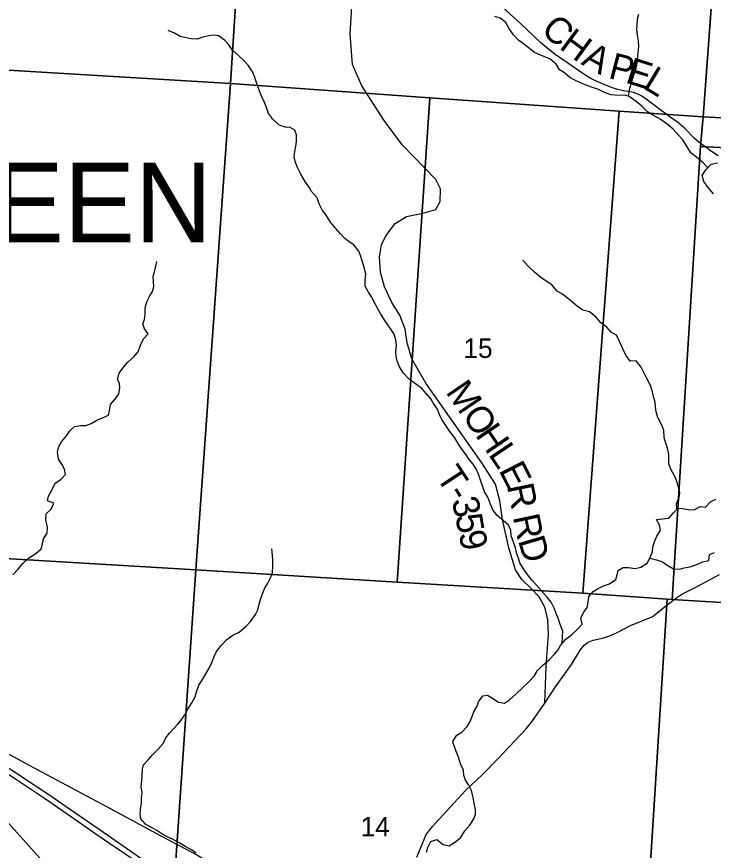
# Model space of a CAD drawing. Extents: x 39.8 to 73.8, y 13 to 35.
# Drawn here: x 45.973 to 47.463, y 29.389 to 31.174 of the extents above; entities that cross this region are included whole.
import ezdxf

# ---------------------------------------------------------------- set-up
doc = ezdxf.new("R2010")
doc.units = 0
for name, color, linetype in [('GM_X_Corporation', 7, 'Continuous'), ('GM_X_County_Road', 7, 'Continuous'), ('GM_X_Minor_River', 7, 'Continuous'), ('GM_X_Rail_Line', 7, 'Continuous'), ('GM_X_Section_Text', 7, 'Continuous'), ('GM_X_State_Route', 7, 'Continuous'), ('GM_X_Township_Road', 7, 'Continuous'), ('GM_X_Township_Road_Text', 7, 'Continuous'), ('GM_X_Township_Text', 7, 'Continuous'), ('GM_X_US_Route', 7, 'Continuous')]:
    doc.layers.add(name, color=color, linetype=linetype)

msp = doc.modelspace()

# ---------------------------------------------------------------- linework, layer by layer
at = {"layer": 'GM_X_Corporation'}
for points in [[(46.4973, 32.0662), (46.4309, 31.0306), (45.4314, 31.091), (45.5069, 32.1262)], [(46.4973, 32.0662), (47.514, 31.9975), (47.4987, 31.7536), (47.4692, 31.3373), (47.4415, 30.9593), (47.2622, 30.9716), (46.8571, 31.0001), (46.4309, 31.0306)], [(47.4692, 31.3373), (48.4841, 31.2738), (48.4569, 30.9045), (47.4415, 30.9593)], [(45.4314, 31.091), (46.4309, 31.0306), (46.3565, 29.9898), (45.3612, 30.049), (45.3568, 30.0492)], [(46.8571, 31.0001), (46.7869, 29.9637), (46.3565, 29.9898), (46.4309, 31.0306)], [(47.2622, 30.9716), (47.1839, 29.9397), (46.7869, 29.9637), (46.8571, 31.0001)], [(47.4415, 30.9593), (47.4356, 30.8958), (47.3755, 29.9267), (47.3645, 29.9274), (47.1839, 29.9397), (47.2622, 30.9716)], [(47.4415, 30.9593), (48.4569, 30.9045), (48.4524, 30.8427), (48.1497, 30.8585), (47.6837, 30.8829), (47.4356, 30.8958)], [(47.6837, 30.8829), (47.6104, 29.9124), (47.3755, 29.9267), (47.4356, 30.8958)], [(45.3612, 30.049), (46.3565, 29.9898), (46.2858, 28.9647), (45.2916, 29.0179)], [(46.3565, 29.9898), (46.7869, 29.9637), (47.1839, 29.9397), (47.3645, 29.9274), (47.3001, 28.9116), (46.2858, 28.9647)], [(47.3645, 29.9274), (47.3755, 29.9267), (47.6104, 29.9124), (48.0851, 29.8835), (48.3814, 29.8655), (48.3118, 28.8573), (47.3001, 28.9116)]]:
    msp.add_lwpolyline(points, close=True, dxfattribs=at)
at = {"layer": 'GM_X_County_Road'}
msp.add_lwpolyline([(45.8429, 29.6563), (45.8641, 29.6449), (46.0264, 29.5578), (46.1656, 29.4834), (46.282, 29.4208), (46.3589, 29.3795), (46.3727, 29.3714), (46.3799, 29.3664)], dxfattribs=at)
at = {"layer": 'GM_X_Minor_River'}
for p, q in [((47.3015, 31.1688), (47.3037, 31.179)), ((47.0076, 31.1709), (46.9959, 31.1746)), ((47.0194, 31.1618), (47.0076, 31.1709)), ((47.0259, 31.1497), (47.0194, 31.1618)), ((47.3004, 31.1566), (47.3015, 31.1688)), ((47.0358, 31.1353), (47.0259, 31.1497)), ((47.2997, 31.1472), (47.3004, 31.1566)), ((47.3009, 31.1343), (47.2997, 31.1472)), ((47.0472, 31.1232), (47.0358, 31.1353)), ((47.0601, 31.1134), (47.0472, 31.1232)), ((47.3032, 31.1214), (47.3009, 31.1343)), ((47.0707, 31.1051), (47.0601, 31.1134)), ((47.081, 31.0975), (47.0707, 31.1051)), ((47.3025, 31.0963), (47.304, 31.1108)), ((47.304, 31.1108), (47.3032, 31.1214)), ((47.0909, 31.093), (47.081, 31.0975)), ((47.1144, 31.0832), (47.0909, 31.093)), ((47.3011, 31.0831), (47.3025, 31.0963)), ((47.1269, 31.0723), (47.1144, 31.0832)), ((47.1346, 31.0601), (47.1269, 31.0723)), ((47.2966, 31.058), (47.2996, 31.0702)), ((47.2996, 31.0702), (47.3011, 31.0831)), ((47.1448, 31.0537), (47.1346, 31.0601)), ((47.1566, 31.0435), (47.1448, 31.0537)), ((47.2929, 31.047), (47.2966, 31.058)), ((47.1668, 31.0382), (47.1566, 31.0435)), ((47.1858, 31.0292), (47.1668, 31.0382)), ((47.2884, 31.0326), (47.2929, 31.047)), ((47.2048, 31.0224), (47.1858, 31.0292)), ((47.2181, 31.0179), (47.2048, 31.0224)), ((47.2321, 31.0108), (47.2181, 31.0179)), ((47.2819, 31.0037), (47.2851, 31.0208)), ((47.2851, 31.0208), (47.2884, 31.0326)), ((47.2446, 31.007), (47.2321, 31.0108)), ((47.2598, 31.0052), (47.2446, 31.007)), ((47.2738, 31.0056), (47.2598, 31.0052)), ((47.2836, 31.0033), (47.2738, 31.0056)), ((47.2981, 30.9924), (47.2836, 31.0033)), ((47.3102, 30.9822), (47.2981, 30.9924)), ((47.3224, 30.9705), (47.3102, 30.9822)), ((47.3357, 30.9625), (47.3224, 30.9705)), ((47.3493, 30.9546), (47.3357, 30.9625)), ((47.3649, 30.944), (47.3493, 30.9546)), ((47.3778, 30.9331), (47.3649, 30.944)), ((47.3893, 30.9198), (47.3778, 30.9331)), ((47.398, 30.91), (47.3893, 30.9198)), ((47.4072, 30.8956), (47.398, 30.91)), ((47.4155, 30.8824), (47.4072, 30.8956)), ((47.4277, 30.8729), (47.4155, 30.8824)), ((47.4418, 30.8612), (47.4277, 30.8729)), ((47.4514, 30.8507), (47.4418, 30.8612)), ((47.4471, 30.8461), (47.4588, 30.8586)), ((47.4588, 30.8586), (47.4724, 30.8609)), ((47.4396, 30.8343), (47.4471, 30.8461)), ((47.4431, 30.821), (47.4396, 30.8343)), ((47.4526, 30.8081), (47.4431, 30.821)), ((47.4636, 30.7949), (47.4526, 30.8081)), ((46.2711, 30.6398), (46.2733, 30.6496)), ((47.0667, 30.6408), (47.056, 30.6529)), ((47.0808, 30.6271), (47.0667, 30.6408)), ((46.2655, 30.6181), (46.2678, 30.6276)), ((46.2678, 30.6276), (46.2711, 30.6398)), ((47.0944, 30.6154), (47.0808, 30.6271)), ((46.2663, 30.6064), (46.2655, 30.6181)), ((46.2668, 30.5961), (46.2663, 30.6064)), ((47.1077, 30.6064), (47.0944, 30.6154)), ((47.1176, 30.5996), (47.1077, 30.6064)), ((46.2638, 30.5855), (46.2668, 30.5961)), ((47.1294, 30.5863), (47.1176, 30.5996)), ((46.2518, 30.5634), (46.2578, 30.5748)), ((46.2578, 30.5748), (46.2638, 30.5855)), ((47.1404, 30.5799), (47.1294, 30.5863)), ((47.151, 30.572), (47.1404, 30.5799)), ((47.1632, 30.5622), (47.151, 30.572)), ((46.2484, 30.5509), (46.2518, 30.5634)), ((47.1731, 30.5535), (47.1632, 30.5622)), ((47.1845, 30.5455), (47.1731, 30.5535)), ((46.247, 30.5259), (46.2481, 30.5373)), ((46.2481, 30.5373), (46.2484, 30.5509)), ((47.1985, 30.5418), (47.1845, 30.5455)), ((47.2118, 30.5312), (47.1985, 30.5418)), ((46.2429, 30.5164), (46.247, 30.5259)), ((46.2467, 30.5058), (46.2429, 30.5164)), ((47.2225, 30.5183), (47.2118, 30.5312)), ((47.2354, 30.5093), (47.2225, 30.5183)), ((46.2547, 30.4952), (46.2467, 30.5058)), ((47.2449, 30.4987), (47.2354, 30.5093)), ((47.2559, 30.4919), (47.2449, 30.4987)), ((46.2381, 30.4708), (46.2445, 30.4845)), ((46.2445, 30.4845), (46.2547, 30.4952)), ((47.2624, 30.4786), (47.2559, 30.4919)), ((46.2329, 30.4564), (46.2381, 30.4708)), ((47.27, 30.4627), (47.2624, 30.4786)), ((47.2762, 30.4495), (47.27, 30.4627)), ((46.211, 30.4347), (46.2231, 30.4454)), ((46.2231, 30.4454), (46.2329, 30.4564)), ((47.2857, 30.4362), (47.2762, 30.4495)), ((46.2024, 30.4244), (46.211, 30.4347)), ((47.2986, 30.4374), (47.2857, 30.4362)), ((47.3088, 30.4238), (47.2986, 30.4374)), ((46.1892, 30.3982), (46.1926, 30.4111)), ((46.1926, 30.4111), (46.2024, 30.4244)), ((47.3157, 30.4105), (47.3088, 30.4238)), ((47.3214, 30.3992), (47.3157, 30.4105)), ((46.1934, 30.3888), (46.1892, 30.3982)), ((47.3287, 30.3844), (47.3214, 30.3992)), ((46.1916, 30.366), (46.1939, 30.3793)), ((46.1939, 30.3793), (46.1934, 30.3888)), ((47.3333, 30.3708), (47.3287, 30.3844)), ((46.1826, 30.3538), (46.1916, 30.366)), ((47.336, 30.3582), (47.3333, 30.3708)), ((47.3387, 30.3488), (47.336, 30.3582)), ((46.1721, 30.3307), (46.1739, 30.3436)), ((46.1739, 30.3436), (46.1826, 30.3538)), ((47.3399, 30.3381), (47.3387, 30.3488)), ((47.3411, 30.3279), (47.3399, 30.3381)), ((46.157, 30.3151), (46.1695, 30.3212)), ((46.1695, 30.3212), (46.1721, 30.3307)), ((47.3441, 30.3184), (47.3411, 30.3279)), ((46.1211, 30.2986), (46.1328, 30.3028)), ((46.1328, 30.3028), (46.1449, 30.3101)), ((46.1449, 30.3101), (46.157, 30.3151)), ((47.348, 30.3086), (47.3441, 30.3184)), ((47.3537, 30.298), (47.348, 30.3086)), ((46.0799, 30.2765), (46.0871, 30.2871)), ((46.0871, 30.2871), (46.0969, 30.2967)), ((46.0969, 30.2967), (46.1101, 30.2986)), ((46.1101, 30.2986), (46.1211, 30.2986)), ((47.3575, 30.2881), (47.3537, 30.298)), ((47.3583, 30.2733), (47.3575, 30.2881)), ((46.069, 30.2636), (46.0799, 30.2765)), ((47.361, 30.2631), (47.3583, 30.2733)), ((46.0608, 30.2419), (46.0638, 30.2541)), ((46.0638, 30.2541), (46.069, 30.2636)), ((47.3652, 30.2502), (47.361, 30.2631)), ((47.3683, 30.2377), (47.3652, 30.2502)), ((46.0627, 30.2271), (46.0608, 30.2419)), ((47.3684, 30.2271), (47.3683, 30.2377)), ((46.0696, 30.2161), (46.0627, 30.2271)), ((46.0753, 30.2052), (46.0696, 30.2161)), ((47.368, 30.2169), (47.3684, 30.2271)), ((47.3734, 30.2036), (47.368, 30.2169)), ((46.0776, 30.1942), (46.0753, 30.2052)), ((47.3806, 30.1911), (47.3734, 30.2036)), ((46.0554, 30.1751), (46.0675, 30.1831)), ((46.0675, 30.1831), (46.0776, 30.1942)), ((47.3845, 30.1809), (47.3806, 30.1911)), ((47.3891, 30.1676), (47.3845, 30.1809)), ((46.0415, 30.1474), (46.049, 30.1618)), ((46.049, 30.1618), (46.0554, 30.1751)), ((47.3914, 30.1547), (47.3891, 30.1676)), ((46.0393, 30.1379), (46.0415, 30.1474)), ((47.3847, 30.1319), (47.3903, 30.1448)), ((47.3903, 30.1448), (47.3914, 30.1547)), ((46.0529, 30.1323), (46.0393, 30.1379)), ((46.0469, 30.1197), (46.0529, 30.1323)), ((47.3851, 30.1192), (47.3847, 30.1319)), ((46.0357, 30.0969), (46.0364, 30.1098)), ((46.0364, 30.1098), (46.0469, 30.1197)), ((46.0391, 30.0814), (46.0357, 30.0969)), ((46.0388, 30.0685), (46.0391, 30.0814)), ((46.0287, 30.0457), (46.0305, 30.0559)), ((46.0305, 30.0559), (46.0388, 30.0685)), ((46.014, 30.0248), (46.0257, 30.0351)), ((46.0257, 30.0351), (46.0287, 30.0457)), ((46.5203, 30.0211), (46.5191, 30.0347)), ((45.9985, 30.0145), (46.014, 30.0248)), ((46.5211, 30.0104), (46.5203, 30.0211)), ((47.4534, 30.01), (47.4548, 30.0225)), ((47.4548, 30.0225), (47.4658, 30.0271)), ((45.9767, 29.9913), (45.9872, 30.0038)), ((45.9872, 30.0038), (45.9985, 30.0145)), ((46.5215, 29.9976), (46.5211, 30.0104)), ((47.3273, 30.0149), (47.3417, 30.0112)), ((47.3417, 30.0112), (47.3549, 30.0067)), ((47.3549, 30.0067), (47.3644, 29.9999)), ((47.3644, 29.9999), (47.3781, 29.9919)), ((47.4141, 29.9962), (47.428, 30.0016)), ((47.428, 30.0016), (47.4405, 30.0073)), ((47.4405, 30.0073), (47.4534, 30.01)), ((45.9654, 29.9795), (45.9767, 29.9913)), ((46.5171, 29.974), (46.5204, 29.9839)), ((46.5204, 29.9839), (46.5215, 29.9976)), ((47.3781, 29.9919), (47.391, 29.9916)), ((47.391, 29.9916), (47.4012, 29.9939)), ((47.4012, 29.9939), (47.4141, 29.9962)), ((46.5107, 29.9611), (46.5171, 29.974)), ((46.4991, 29.9383), (46.5039, 29.9516)), ((46.5039, 29.9516), (46.5107, 29.9611)), ((46.4949, 29.9265), (46.4991, 29.9383)), ((46.4894, 29.9045), (46.492, 29.9167)), ((46.492, 29.9167), (46.4949, 29.9265)), ((46.4732, 29.879), (46.4845, 29.8939)), ((46.4845, 29.8939), (46.4894, 29.9045)), ((46.4641, 29.8692), (46.4732, 29.879)), ((46.4354, 29.8501), (46.4494, 29.8566)), ((46.4494, 29.8566), (46.4641, 29.8692)), ((46.4117, 29.8288), (46.423, 29.841)), ((46.423, 29.841), (46.4354, 29.8501)), ((46.4008, 29.8151), (46.4117, 29.8288)), ((46.3914, 29.7931), (46.3959, 29.8041)), ((46.3959, 29.8041), (46.4008, 29.8151)), ((46.3854, 29.7794), (46.3914, 29.7931)), ((46.3703, 29.7539), (46.3782, 29.7672)), ((46.3782, 29.7672), (46.3854, 29.7794)), ((46.3628, 29.7433), (46.3703, 29.7539)), ((46.3583, 29.7285), (46.3628, 29.7433)), ((46.3482, 29.7049), (46.355, 29.7178)), ((46.355, 29.7178), (46.3583, 29.7285)), ((46.3396, 29.6916), (46.3482, 29.7049)), ((46.3253, 29.6684), (46.3332, 29.6794)), ((46.3332, 29.6794), (46.3396, 29.6916)), ((46.3174, 29.6589), (46.3253, 29.6684)), ((46.3, 29.6399), (46.3174, 29.6589)), ((46.2865, 29.6181), (46.2925, 29.63)), ((46.2925, 29.63), (46.3, 29.6399)), ((46.264, 29.5936), (46.276, 29.6062)), ((46.276, 29.6062), (46.2865, 29.6181)), ((46.9128, 29.6029), (46.9071, 29.6194)), ((46.2554, 29.584), (46.264, 29.5936)), ((46.9186, 29.5889), (46.9128, 29.6029)), ((46.9225, 29.5749), (46.9186, 29.5889)), ((46.2427, 29.5631), (46.2449, 29.5725)), ((46.2449, 29.5725), (46.2554, 29.584)), ((46.9287, 29.5613), (46.9225, 29.5749)), ((46.2417, 29.5494), (46.2427, 29.5631)), ((46.9299, 29.5496), (46.9287, 29.5613)), ((46.2396, 29.5263), (46.241, 29.5388)), ((46.241, 29.5388), (46.2417, 29.5494)), ((46.9334, 29.5398), (46.9299, 29.5496)), ((46.9407, 29.5292), (46.9334, 29.5398)), ((46.2416, 29.5126), (46.2396, 29.5263)), ((46.9461, 29.5172), (46.9407, 29.5292)), ((46.95, 29.5028), (46.9461, 29.5172)), ((46.2403, 29.491), (46.2406, 29.5009)), ((46.2406, 29.5009), (46.2416, 29.5126)), ((46.952, 29.4907), (46.95, 29.5028)), ((46.2385, 29.477), (46.2403, 29.491)), ((46.9547, 29.4767), (46.952, 29.4907)), ((46.2375, 29.4671), (46.2385, 29.477)), ((46.2391, 29.4569), (46.2375, 29.4671)), ((46.9511, 29.4566), (46.9548, 29.4661)), ((46.9548, 29.4661), (46.9547, 29.4767)), ((46.249, 29.4456), (46.2391, 29.4569)), ((46.2631, 29.4378), (46.249, 29.4456)), ((46.9426, 29.4436), (46.9511, 29.4566)), ((46.273, 29.4318), (46.2631, 29.4378)), ((46.2863, 29.4236), (46.273, 29.4318)), ((46.9224, 29.4165), (46.9321, 29.431)), ((46.9321, 29.431), (46.9426, 29.4436)), ((46.2965, 29.4176), (46.2863, 29.4236)), ((46.3064, 29.4136), (46.2965, 29.4176)), ((46.322, 29.405), (46.3064, 29.4136)), ((46.8589, 29.408), (46.8721, 29.4123)), ((46.8721, 29.4123), (46.8854, 29.4022)), ((46.91, 29.4062), (46.9224, 29.4165)), ((46.3353, 29.3972), (46.322, 29.405)), ((46.3475, 29.3908), (46.3353, 29.3972)), ((46.8496, 29.3855), (46.8529, 29.3958)), ((46.8529, 29.3958), (46.8589, 29.408)), ((46.8854, 29.4022), (46.8983, 29.3989)), ((46.8983, 29.3989), (46.91, 29.4062)), ((46.357, 29.3837), (46.3475, 29.3908))]:
    msp.add_line(p, q, dxfattribs=at)
for points in [[(46.4921, 31.0168), (46.4872, 31.0312), (46.4818, 31.0459), (46.478, 31.0562), (46.4688, 31.0705), (46.4593, 31.08), (46.4475, 31.0906), (46.4346, 31.1027), (46.427, 31.1137), (46.4179, 31.1235), (46.4049, 31.1333), (46.3947, 31.1344), (46.3841, 31.1329), (46.3716, 31.1298), (46.3595, 31.126), (46.3463, 31.1267), (46.333, 31.1293), (46.3232, 31.1315), (46.3106, 31.1387), (46.2977, 31.1444)], [(47.1398, 29.8317), (47.1409, 29.847), (47.1412, 29.8588), (47.1359, 29.8728), (47.132, 29.8846), (47.1274, 29.8963), (47.1236, 29.9065), (47.1167, 29.9209), (47.108, 29.9315), (47.0958, 29.9448), (47.0851, 29.9569), (47.076, 29.9667), (47.0661, 29.9796), (47.0585, 29.9902), (47.0497, 30.0049), (47.0463, 30.0148), (47.0432, 30.0242), (47.0401, 30.0371), (47.0363, 30.0493), (47.0309, 30.0625), (47.0301, 30.075), (47.0255, 30.0853), (47.0137, 30.0958), (47.0008, 30.1064), (46.9921, 30.1182), (46.9863, 30.1322), (46.9817, 30.1439), (46.9737, 30.1568), (46.9706, 30.1674), (46.966, 30.1795), (46.9611, 30.1947), (46.9561, 30.2061), (46.95, 30.2159), (46.9409, 30.2257), (46.9348, 30.236), (46.9256, 30.2484), (46.9184, 30.2587), (46.9107, 30.2727), (46.9001, 30.2863), (46.8913, 30.2988), (46.8829, 30.312), (46.8772, 30.3238), (46.8734, 30.3336), (46.865, 30.3461), (46.8589, 30.356), (46.8501, 30.3666), (46.8402, 30.3779), (46.8129, 30.3983), (46.8007, 30.4108), (46.7919, 30.4244), (46.787, 30.4373), (46.785, 30.4468), (46.7842, 30.4566), (46.7857, 30.4699), (46.7841, 30.482), (46.781, 30.4942), (46.7723, 30.5074), (46.7624, 30.5214), (46.7521, 30.537), (46.7467, 30.5472), (46.7399, 30.5593), (46.7322, 30.5741), (46.7261, 30.5839), (46.7189, 30.5972), (46.7188, 30.6101), (46.7199, 30.623), (46.7168, 30.6377), (46.713, 30.6487), (46.7084, 30.6628), (46.7049, 30.6722), (46.6946, 30.6859), (46.6844, 30.6923), (46.6749, 30.6991), (46.6654, 30.71), (46.6551, 30.721), (46.6448, 30.7343), (46.6353, 30.7494), (46.6273, 30.7592), (46.6204, 30.7736), (46.6158, 30.7865), (46.6037, 30.7994), (46.5987, 30.8092), (46.5911, 30.8194), (46.5812, 30.8365), (46.5743, 30.8512), (46.5697, 30.8615), (46.5666, 30.874), (46.5681, 30.8854), (46.5707, 30.8971), (46.5721, 30.9066), (46.5721, 30.9207), (46.5682, 30.9309), (46.558, 30.9369), (46.5485, 30.9377), (46.5345, 30.9414), (46.5204, 30.9554), (46.5121, 30.9667), (46.5075, 30.9796), (46.5032, 30.9899), (46.4979, 31.0027), (46.4921, 31.0168)], [(46.9071, 29.6194), (46.9071, 29.6236), (46.9146, 29.6358), (46.9252, 29.6426), (46.9372, 29.6548), (46.9436, 29.6651), (46.9466, 29.6746), (46.9519, 29.6871), (46.9579, 29.6977), (46.9613, 29.7076), (46.9707, 29.7198), (46.9805, 29.7217), (46.9915, 29.7142), (47.0037, 29.7066), (47.0166, 29.7044), (47.0275, 29.7116), (47.0411, 29.7238), (47.0554, 29.7371), (47.069, 29.7504), (47.0799, 29.7619), (47.0874, 29.7744), (47.0988, 29.7858), (47.1123, 29.7972), (47.124, 29.809), (47.1312, 29.8185), (47.1368, 29.828), (47.1477, 29.8414), (47.1602, 29.8509), (47.1723, 29.8619), (47.1828, 29.8737), (47.1801, 29.887), (47.1865, 29.8995), (47.1933, 29.909), (47.1955, 29.9208), (47.197, 29.9329), (47.206, 29.9436), (47.2158, 29.9489), (47.2287, 29.9558), (47.2415, 29.9596), (47.2551, 29.9692), (47.2574, 29.979), (47.26, 29.9885), (47.2702, 29.9946), (47.2819, 29.9947), (47.2963, 29.9928), (47.308, 29.9959), (47.322, 30.0043), (47.328, 30.0164), (47.3329, 30.0282), (47.3343, 30.0388), (47.3381, 30.0521), (47.3426, 30.0616), (47.3505, 30.0742), (47.3482, 30.0863), (47.3417, 30.0973), (47.3553, 30.0988), (47.3685, 30.1004), (47.3783, 30.1122), (47.3878, 30.1221), (47.3976, 30.1214), (47.4094, 30.1191), (47.4222, 30.118), (47.4351, 30.1253), (47.4464, 30.1242), (47.457, 30.1356), (47.4687, 30.1413)]]:
    msp.add_lwpolyline(points, dxfattribs=at)
at = {"layer": 'GM_X_Rail_Line'}
msp.add_lwpolyline([(44.5671, 30.953), (44.7292, 30.8182), (45.0124, 30.5825), (45.1026, 30.5077), (45.1987, 30.4263), (45.2077, 30.4171), (45.22, 30.4044), (45.2312, 30.3923), (45.2411, 30.381), (45.2642, 30.3518), (45.5741, 29.9214), (45.6686, 29.79), (45.7115, 29.7307), (45.7298, 29.7054), (45.754, 29.6754), (45.794, 29.6292), (45.8686, 29.5449), (45.9623, 29.4402), (46.0662, 29.3238)], dxfattribs=at)
at = {"layer": 'GM_X_State_Route'}
msp.add_lwpolyline([(46.8289, 29.3747), (46.8426, 29.4074), (46.8492, 29.4234), (46.8629, 29.4406), (46.8919, 29.4725), (46.934, 29.5183), (46.969, 29.5511), (47.0035, 29.5859), (47.0628, 29.6493), (47.0689, 29.6569), (47.0767, 29.6665), (47.1027, 29.7045), (47.1259, 29.7392), (47.16, 29.787), (47.1784, 29.8177), (47.1874, 29.8283), (47.1956, 29.8347), (47.2067, 29.8394), (47.2293, 29.8444), (47.2436, 29.8492), (47.258, 29.8555), (47.2878, 29.8715), (47.3325, 29.889), (47.3458, 29.9), (47.3617, 29.9128), (47.3821, 29.9287), (47.3974, 29.9385), (47.4277, 29.9535), (47.4764, 29.9798)], dxfattribs=at)
at = {"layer": 'GM_X_Township_Road'}
for points in [[(46.7659, 30.5835), (46.7602, 30.5957), (46.7513, 30.6268), (46.7495, 30.6599), (46.7534, 30.6858), (46.7632, 30.7048), (46.7831, 30.7312), (46.8069, 30.7462), (46.8448, 30.754), (46.8701, 30.761), (46.8791, 30.7782), (46.88, 30.8055), (46.8696, 30.8252), (46.7988, 30.8992), (46.7592, 30.9518), (46.7116, 31.026), (46.6918, 31.0718), (46.6867, 31.1371), (46.6921, 31.2314), (46.7002, 31.2793)], [(47.2152, 31.035), (47.21, 31.0374), (47.2017, 31.0417), (47.191, 31.048), (47.1705, 31.0616), (47.145, 31.0792), (47.1249, 31.0933), (47.115, 31.1008), (47.103, 31.1107), (47.0938, 31.119), (47.0508, 31.1595), (46.9983, 31.2075)], [(47.4739, 30.8761), (47.4617, 30.8841), (47.4544, 30.8892), (47.4522, 30.891), (47.4452, 30.8959), (47.4428, 30.8974), (47.4333, 30.9044), (47.4222, 30.9136), (47.4178, 30.9179), (47.4074, 30.9295), (47.4008, 30.936), (47.3962, 30.9402), (47.3864, 30.9478), (47.3713, 30.9588), (47.3587, 30.9679), (47.3543, 30.9712), (47.3338, 30.9864), (47.3165, 30.9995), (47.3091, 31.0045), (47.304, 31.0073), (47.2983, 31.0096), (47.2923, 31.0114), (47.2862, 31.0128), (47.2709, 31.0154), (47.2588, 31.0182), (47.25, 31.0208), (47.2385, 31.0251), (47.2213, 31.0322), (47.2152, 31.035)], [(47.1027, 29.7045), (47.1059, 29.7825), (47.1106, 29.8525), (47.1096, 29.8825), (47.1033, 29.9102), (47.0906, 29.9322), (47.073, 29.9507), (47.0535, 29.9692), (47.0404, 29.9896), (47.026, 30.037), (47.0126, 30.0973), (47.0069, 30.1376), (46.9975, 30.1736), (46.9679, 30.2186), (46.8485, 30.3896), (46.8188, 30.4415), (46.8087, 30.476), (46.8039, 30.5052), (46.7926, 30.5348), (46.7757, 30.5624), (46.7696, 30.5756), (46.7659, 30.5835)]]:
    msp.add_lwpolyline(points, dxfattribs=at)
at = {"layer": 'GM_X_US_Route'}
for points in [[(45.8288, 29.6328), (45.8611, 29.6174), (45.8944, 29.6003), (45.9218, 29.5857), (45.9422, 29.5742), (45.9658, 29.5595), (45.9817, 29.5492), (46.0418, 29.5089), (46.0975, 29.4705), (46.1516, 29.433), (46.2155, 29.3891), (46.2813, 29.3437), (46.3223, 29.3156)], [(45.8248, 29.6216), (45.8423, 29.6131), (45.8712, 29.5989), (45.9063, 29.581), (45.9326, 29.5658), (45.9568, 29.5514), (45.9728, 29.5411), (46.0328, 29.5008), (46.0886, 29.4625), (46.1427, 29.4249), (46.1696, 29.4065)], [(46.1696, 29.4065), (46.2065, 29.381), (46.2723, 29.3356), (46.3117, 29.3082)]]:
    msp.add_lwpolyline(points, dxfattribs=at)

# ---------------------------------------------------------------- texts
at = {"layer": 'GM_X_Section_Text'}
for s, p in [('15', (46.929, 30.4434)), ('14', (46.709, 29.4191))]:
    msp.add_text(s, height=0.04186, rotation=0, dxfattribs=at).set_placement(p)
at = {"layer": 'GM_X_Township_Road_Text'}
for s, rotation, p in [('C', 317.9101, (47.0922, 31.1421)), ('H', 323.5018, (47.1315, 31.107)), ('A', 331.0109, (47.1785, 31.0729)), ('P', 345.4531, (47.2368, 31.0429)), ('E', 342.4108, (47.2731, 31.0335)), ('L', 328.9223, (47.3104, 31.0221)), ('M', 304.3029, (46.8898, 30.3707)), ('O', 304.3062, (46.9246, 30.3198)), ('H', 304.3062, (46.9528, 30.2785)), ('L', 303.8755, (46.9809, 30.2372)), ('T', 303.3287, (46.8689, 30.1894)), ('E', 296.8775, (47.0036, 30.2035)), ('-', 301.7241, (46.8921, 30.1542)), ('R', 281.8879, (47.0216, 30.1693)), ('3', 285.1963, (46.9026, 30.1383)), ('5', 279.7156, (46.9115, 30.106)), ('R', 282.0175, (47.0343, 30.1035)), ('9', 282.9245, (46.9181, 30.0681)), ('D', 286.5363, (47.0452, 30.0531))]:
    msp.add_text(s, height=0.0568, rotation=rotation, dxfattribs=at).set_placement(p)
at = {"layer": 'GM_X_Township_Text'}
msp.add_text('GREEN', height=0.17045, rotation=0, dxfattribs=at).set_placement((45.5803, 30.6907))

doc.saveas('drawing.dxf')
